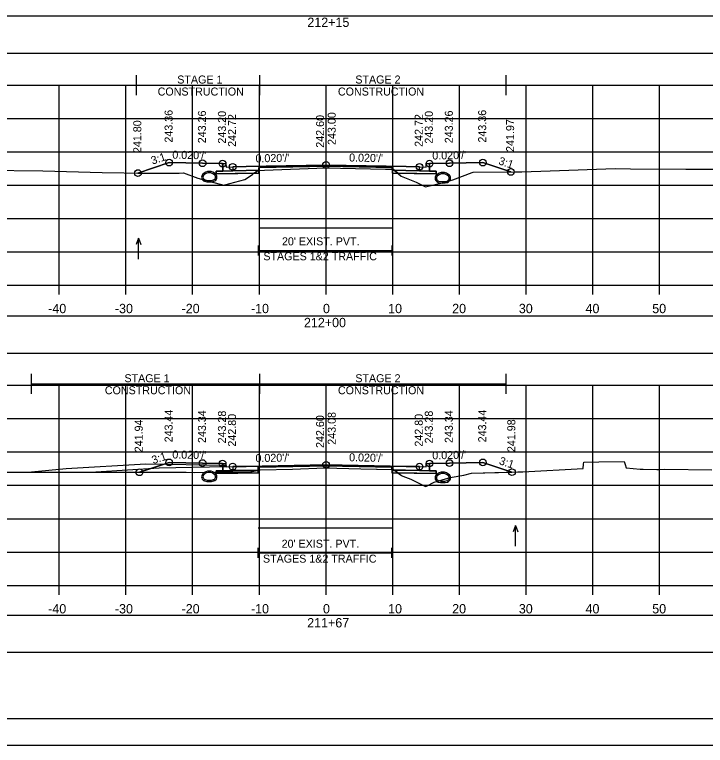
# Model space of a CAD drawing. Extents: x 1369627 to 1374022, y 380035 to 398173.
# Drawn here: x 1372051.8 to 1372155.4, y 382598.8 to 382708.4 of the extents above; entities that cross this region are included whole.
import ezdxf

# ---------------------------------------------------------------- set-up
doc = ezdxf.new("R2010")
doc.units = 0
for name, color, linetype in [('Default', 7, 'Continuous'), ('R_Alt Surface', 7, 'Continuous'), ('R_Axis', 7, 'Continuous'), ('R_Axis Annot', 7, 'Continuous'), ('R_Border', 7, 'Continuous'), ('R_Drive', 7, 'Continuous'), ('R_Exist Surface', 7, 'Continuous'), ('R_Fin Surface', 7, 'Continuous'), ('R_Grid', 7, 'Continuous'), ('R_MOT', 7, 'Continuous'), ('R_No Plot', 7, 'Continuous'), ('R_Water Annot', 7, 'Continuous'), ('R_Xsect Elev', 7, 'Continuous'), ('R_Xsect Slope', 7, 'Continuous'), ('T_Vehicle Path Lt Minor', 7, 'Continuous'), ('T_Vehicle Path Rt', 7, 'Continuous')]:
    doc.layers.add(name, color=color, linetype=linetype)

msp = doc.modelspace()

# ---------------------------------------------------------------- linework, layer by layer
at = {"layer": 'Default'}
for p, q in [((1372088.42, 382672.27), (1372088.42, 382673.77)), ((1372088.42, 382673.02), (1372108.42, 382673.02)), ((1372108.42, 382672.27), (1372108.42, 382673.77)), ((1372088.37, 382626.96), (1372088.37, 382628.46)), ((1372108.37, 382626.96), (1372108.37, 382628.46)), ((1372088.37, 382627.71), (1372108.37, 382627.71))]:
    msp.add_line(p, q, dxfattribs=at)
for points in [[(1371948.53, 382702.6), (1372248.53, 382702.6), (1372248.53, 382708.12), (1371948.53, 382708.12)], [(1372083.02, 382686.02), (1372083.52, 382686.02), (1372083.53, 382685.52), (1372084.53, 382685.54), (1372084.53, 382684.95), (1372083.03, 382684.92)], [(1372113.53, 382685.52), (1372113.54, 382686.02), (1372114.04, 382686.02), (1372114.03, 382684.92), (1372112.53, 382684.95), (1372112.53, 382685.54)], [(1371948.53, 382657.63), (1372248.53, 382657.63), (1372248.53, 382663.15), (1371948.53, 382663.15)], [(1372083.02, 382641.09), (1372083.52, 382641.09), (1372083.53, 382640.59), (1372084.53, 382640.61), (1372084.53, 382640.02), (1372083.03, 382639.99)], [(1372113.53, 382640.59), (1372113.54, 382641.09), (1372114.04, 382641.09), (1372114.03, 382639.99), (1372112.53, 382640.02), (1372112.53, 382640.61)], [(1371948.53, 382612.78), (1372248.53, 382612.78), (1372248.53, 382618.3), (1371948.53, 382618.3)]]:
    msp.add_lwpolyline(points, close=True, dxfattribs=at)
at = {"layer": 'R_Alt Surface'}
for points in [[(1372082.03, 382684.9), (1372083.03, 382684.92), (1372084.53, 382684.95), (1372088.43, 382685.03), (1372088.43, 382684.61), (1372082.03, 382684.48)], [(1372115.03, 382684.9), (1372114.03, 382684.92), (1372112.53, 382684.95), (1372108.43, 382685.03), (1372108.43, 382684.62), (1372115.03, 382684.48)], [(1372082.03, 382639.97), (1372083.03, 382639.99), (1372084.53, 382640.02), (1372088.37, 382640.1), (1372088.37, 382639.68), (1372082.03, 382639.56)], [(1372115.03, 382639.97), (1372114.03, 382639.99), (1372112.53, 382640.02), (1372108.37, 382640.11), (1372108.37, 382639.69), (1372115.03, 382639.56)]]:
    msp.add_lwpolyline(points, close=True, dxfattribs=at)
for points in [[(1372083.03, 382686.02), (1372083.03, 382684.92), (1372084.53, 382684.95), (1372088.43, 382685.03), (1372088.43, 382685.45), (1372098.53, 382685.65), (1372108.43, 382685.45), (1372108.43, 382685.03), (1372112.53, 382684.95), (1372114.03, 382684.92), (1372114.03, 382686.02)], [(1372083.03, 382641.09), (1372083.03, 382639.99), (1372084.53, 382640.02), (1372088.37, 382640.1), (1372088.37, 382640.52), (1372098.53, 382640.72), (1372108.37, 382640.52), (1372108.37, 382640.11), (1372112.53, 382640.02), (1372114.03, 382639.99), (1372114.03, 382641.09)]]:
    msp.add_lwpolyline(points, dxfattribs=at)
at = {"layer": 'R_Axis'}
for p, q in [((1371948.53, 382667.81), (1372248.53, 382667.81)), ((1372058.53, 382666.41), (1372058.53, 382667.81)), ((1372068.53, 382666.41), (1372068.53, 382667.81)), ((1372078.53, 382666.41), (1372078.53, 382667.81)), ((1372088.53, 382666.41), (1372088.53, 382667.81)), ((1372098.53, 382666.41), (1372098.53, 382667.81)), ((1372108.53, 382666.41), (1372108.53, 382667.81)), ((1372118.53, 382666.41), (1372118.53, 382667.81)), ((1372128.53, 382666.41), (1372128.53, 382667.81)), ((1372138.53, 382666.41), (1372138.53, 382667.81)), ((1372148.53, 382666.41), (1372148.53, 382667.81)), ((1371948.53, 382622.81), (1372248.53, 382622.81)), ((1372058.53, 382621.41), (1372058.53, 382622.81)), ((1372068.53, 382621.41), (1372068.53, 382622.81)), ((1372078.53, 382621.41), (1372078.53, 382622.81)), ((1372088.53, 382621.41), (1372088.53, 382622.81)), ((1372098.53, 382621.41), (1372098.53, 382622.81)), ((1372108.53, 382621.41), (1372108.53, 382622.81)), ((1372118.53, 382621.41), (1372118.53, 382622.81)), ((1372128.53, 382621.41), (1372128.53, 382622.81)), ((1372138.53, 382621.41), (1372138.53, 382622.81)), ((1372148.53, 382621.41), (1372148.53, 382622.81))]:
    msp.add_line(p, q, dxfattribs=at)
at = {"layer": 'R_Border'}
msp.add_line((1372256.71, 382602.81), (1371940.53, 382602.81), dxfattribs=at)
at = {"layer": 'R_Drive'}
for p, q in [((1372059.55, 382640.28), (1372054.37, 382639.76)), ((1372071.53, 382641), (1372059.55, 382640.28))]:
    msp.add_line(p, q, dxfattribs=at)
msp.add_lwpolyline([(1372083.53, 382640.59), (1372083.53, 382640.76), (1372071.53, 382641)], dxfattribs=at)
for centre, radius, start, end in [((1372080.51, 382684), 0.646, 136.3515, 253.9529), ((1372081.02, 382683.51), 1.35, 43.6485, 136.3515), ((1372080.51, 382684), 0.438, 136.3515, 253.9529), ((1372081.02, 382683.51), 1.15, 43.6485, 136.3515), ((1372081.53, 382684), 0.438, 286.0471, 43.6485), ((1372081.53, 382684), 0.646, 286.0471, 43.6485), ((1372115.53, 382683.84), 0.646, 136.3515, 253.9529), ((1372116.04, 382683.35), 1.35, 43.6485, 136.3515), ((1372115.53, 382683.84), 0.438, 136.3515, 253.9529), ((1372116.04, 382683.35), 1.15, 43.6485, 136.3515), ((1372116.55, 382683.84), 0.438, 286.0471, 43.6485), ((1372116.55, 382683.84), 0.646, 286.0471, 43.6485), ((1372081.02, 382685.78), 2.5, 253.9529, 286.0471), ((1372081.02, 382685.78), 2.29, 253.9529, 286.0471), ((1372116.04, 382685.62), 2.5, 253.9529, 286.0471), ((1372116.04, 382685.62), 2.29, 253.9529, 286.0471), ((1372080.51, 382639.08), 0.646, 136.3515, 253.9529), ((1372081.02, 382638.6), 1.35, 43.6485, 136.3515), ((1372080.51, 382639.08), 0.438, 136.3515, 253.9529), ((1372081.02, 382638.6), 1.15, 43.6485, 136.3515), ((1372081.53, 382639.08), 0.438, 286.0471, 43.6485), ((1372081.53, 382639.08), 0.646, 286.0471, 43.6485), ((1372115.53, 382638.92), 0.646, 136.3515, 253.9529), ((1372116.04, 382638.44), 1.35, 43.6485, 136.3515), ((1372115.53, 382638.92), 0.438, 136.3515, 253.9529), ((1372116.04, 382638.44), 1.15, 43.6485, 136.3515), ((1372116.55, 382638.92), 0.438, 286.0471, 43.6485), ((1372116.55, 382638.92), 0.646, 286.0471, 43.6485), ((1372081.02, 382640.87), 2.5, 253.9529, 286.0471), ((1372081.02, 382640.87), 2.29, 253.9529, 286.0471), ((1372116.04, 382640.71), 2.5, 253.9529, 286.0471), ((1372116.04, 382640.71), 2.29, 253.9529, 286.0471)]:
    msp.add_arc(centre, radius, start, end, dxfattribs=at)
at = {"layer": 'R_Exist Surface'}
for points in [[(1372047.35, 382685.06), (1372056.07, 382684.93), (1372064.97, 382684.69), (1372071.52, 382684.6), (1372076.49, 382684.59), (1372077.15, 382684.67), (1372079.33, 382683.86), (1372079.5, 382683.79), (1372079.65, 382683.76), (1372083.18, 382682.79), (1372083.33, 382682.83), (1372086.35, 382683.67), (1372087.48, 382684.42), (1372087.68, 382684.59), (1372088.05, 382684.82), (1372088.32, 382685), (1372089.29, 382685.04), (1372098.43, 382685.42), (1372107.46, 382685.21), (1372108.55, 382685.19), (1372108.7, 382685.08), (1372109.8, 382684.17), (1372112.04, 382683.23), (1372113.44, 382682.57), (1372116.15, 382683.22), (1372117.56, 382683.58), (1372120.42, 382684.69), (1372120.61, 382684.76), (1372126.88, 382684.78), (1372127.87, 382684.81), (1372132.12, 382684.95), (1372141.86, 382685.29), (1372144.17, 382685.26), (1372152.48, 382685.18), (1372158.04, 382685.21)], [(1372048.59, 382639.76), (1372057.66, 382639.76), (1372073.4, 382639.76), (1372077.58, 382639.78), (1372078.84, 382639.72), (1372082.4, 382639.77), (1372082.8, 382639.77), (1372083.45, 382639.81), (1372086.69, 382639.79), (1372086.85, 382639.79), (1372086.97, 382639.79), (1372086.99, 382639.8), (1372088.63, 382640.11), (1372093.49, 382640.25), (1372098.37, 382640.42), (1372103.74, 382640.28), (1372108.64, 382640.16), (1372109.82, 382639.3), (1372110.02, 382639.18), (1372111.23, 382638.72), (1372113.03, 382637.83), (1372113.35, 382637.68), (1372113.44, 382637.64), (1372113.58, 382637.69), (1372114.75, 382638.28), (1372117.13, 382638.97), (1372119.17, 382639.33), (1372120.35, 382639.62), (1372127.31, 382639.82), (1372127.34, 382639.82), (1372127.5, 382639.83), (1372128.02, 382639.85), (1372137.09, 382640.33), (1372137.15, 382640.98), (1372137.18, 382641.29), (1372139.42, 382641.33), (1372143.24, 382641.4), (1372143.4, 382640.91), (1372143.53, 382640.45), (1372145.65, 382640.21), (1372146.07, 382640.22), (1372148.12, 382640.2), (1372148.24, 382640.2), (1372148.43, 382640.2), (1372149.35, 382640.22), (1372156.36, 382640.13)]]:
    msp.add_lwpolyline(points, dxfattribs=at)
at = {"layer": 'R_Fin Surface'}
for points in [[(1372070.33, 382684.61), (1372075.02, 382686.18), (1372080.02, 382686.08), (1372083.02, 382686.02), (1372083.52, 382686.02), (1372083.53, 382685.52), (1372084.53, 382685.54), (1372086.53, 382685.58), (1372098.53, 382685.82), (1372110.53, 382685.58), (1372112.53, 382685.54), (1372113.53, 382685.52), (1372113.54, 382686.02), (1372114.04, 382686.02), (1372117.04, 382686.08), (1372122.04, 382686.18), (1372126.23, 382684.78)], [(1372070.54, 382639.76), (1372075.02, 382641.25), (1372080.02, 382641.15), (1372083.02, 382641.09), (1372083.52, 382641.09), (1372083.53, 382640.59), (1372084.53, 382640.61), (1372086.53, 382640.65), (1372098.53, 382640.89), (1372110.53, 382640.65), (1372112.53, 382640.61), (1372113.53, 382640.59), (1372113.54, 382641.09), (1372114.04, 382641.09), (1372117.04, 382641.15), (1372122.04, 382641.25), (1372126.41, 382639.79)]]:
    msp.add_lwpolyline(points, dxfattribs=at)
at = {"layer": 'R_Grid'}
for p, q in [((1371948.53, 382697.81), (1372248.53, 382697.81)), ((1372058.53, 382667.81), (1372058.53, 382697.81)), ((1372068.53, 382667.81), (1372068.53, 382697.81)), ((1372078.53, 382667.81), (1372078.53, 382697.81)), ((1372088.53, 382667.81), (1372088.53, 382697.81)), ((1372098.53, 382667.81), (1372098.53, 382697.81)), ((1372108.53, 382667.81), (1372108.53, 382697.81)), ((1372118.53, 382667.81), (1372118.53, 382697.81)), ((1372128.53, 382667.81), (1372128.53, 382697.81)), ((1372138.53, 382667.81), (1372138.53, 382697.81)), ((1372148.53, 382667.81), (1372148.53, 382697.81)), ((1371948.53, 382692.81), (1372248.53, 382692.81)), ((1371948.53, 382687.81), (1372248.53, 382687.81)), ((1371948.53, 382682.81), (1372248.53, 382682.81)), ((1371948.53, 382677.81), (1372248.53, 382677.81)), ((1371948.53, 382672.81), (1372248.53, 382672.81)), ((1371948.53, 382667.81), (1372248.53, 382667.81)), ((1371948.53, 382652.81), (1372248.53, 382652.81)), ((1372058.53, 382622.81), (1372058.53, 382652.81)), ((1372068.53, 382622.81), (1372068.53, 382652.81)), ((1372078.53, 382622.81), (1372078.53, 382652.81)), ((1372088.53, 382622.81), (1372088.53, 382652.81)), ((1372098.53, 382622.81), (1372098.53, 382652.81)), ((1372108.53, 382622.81), (1372108.53, 382652.81)), ((1372118.53, 382622.81), (1372118.53, 382652.81)), ((1372128.53, 382622.81), (1372128.53, 382652.81)), ((1372138.53, 382622.81), (1372138.53, 382652.81)), ((1372148.53, 382622.81), (1372148.53, 382652.81)), ((1371948.53, 382647.81), (1372248.53, 382647.81)), ((1371948.53, 382642.81), (1372248.53, 382642.81)), ((1371948.53, 382637.81), (1372248.53, 382637.81)), ((1371948.53, 382632.81), (1372248.53, 382632.81)), ((1371948.53, 382627.81), (1372248.53, 382627.81)), ((1371948.53, 382622.81), (1372248.53, 382622.81))]:
    msp.add_line(p, q, dxfattribs=at)
at = {"layer": 'R_MOT'}
for p, q in [((1372070.11, 382696.27), (1372070.11, 382699.27)), ((1372088.58, 382696.27), (1372088.58, 382699.27)), ((1372125.56, 382696.27), (1372125.56, 382699.27)), ((1372070.11, 382697.77), (1372125.56, 382697.77)), ((1372054.37, 382651.5), (1372054.37, 382654.5)), ((1372088.58, 382651.5), (1372088.58, 382654.5)), ((1372125.56, 382651.5), (1372125.56, 382654.5)), ((1372054.37, 382653), (1372125.56, 382653))]:
    msp.add_line(p, q, dxfattribs=at)
at = {"layer": 'R_No Plot'}
for p, q in [((1372073.53, 382640.39), (1372063.99, 382639.76)), ((1372083.53, 382640.59), (1372073.53, 382640.39)), ((1371928.13, 382598.84), (1372261.46, 382598.84))]:
    msp.add_line(p, q, dxfattribs=at)
for points in [[(1371928.12, 382812.17), (1372261.46, 382812.17), (1372261.46, 382598.83), (1371928.12, 382598.83)], [(1372174.45, 382808.27), (1372194.07, 382808.27), (1372194.07, 382798.39), (1372210.18, 382798.39), (1372233.38, 382798.39), (1372233.38, 382765.72), (1372256.59, 382765.72), (1372256.71, 382602.81), (1371940.53, 382602.81), (1371940.53, 382808.27)], [(1372088.53, 382685.03), (1372084.53, 382684.95), (1372083.03, 382684.92), (1372082.03, 382684.9), (1372082.03, 382684.48), (1372088.53, 382684.61)], [(1372098.53, 382685.82), (1372086.53, 382685.58), (1372084.53, 382685.54), (1372084.53, 382684.95), (1372088.53, 382685.03), (1372088.53, 382685.45), (1372098.53, 382685.65), (1372108.53, 382685.45), (1372108.53, 382685.03), (1372112.53, 382684.95), (1372112.53, 382685.54), (1372110.53, 382685.58)], [(1372108.53, 382685.03), (1372112.53, 382684.95), (1372114.03, 382684.92), (1372115.03, 382684.9), (1372115.03, 382684.48), (1372108.53, 382684.61)], [(1372088.53, 382640.1), (1372084.53, 382640.02), (1372083.03, 382639.99), (1372082.03, 382639.97), (1372082.03, 382639.56), (1372088.53, 382639.69)], [(1372098.53, 382640.89), (1372086.53, 382640.65), (1372084.53, 382640.61), (1372084.53, 382640.02), (1372088.53, 382640.1), (1372088.53, 382640.52), (1372098.53, 382640.72), (1372108.53, 382640.52), (1372108.53, 382640.1), (1372112.53, 382640.02), (1372112.53, 382640.61), (1372110.53, 382640.65)], [(1372108.53, 382640.1), (1372112.53, 382640.02), (1372114.03, 382639.99), (1372115.03, 382639.97), (1372115.03, 382639.56), (1372108.53, 382639.69)]]:
    msp.add_lwpolyline(points, close=True, dxfattribs=at)
for points in [[(1372083.02, 382686.02), (1372083.03, 382684.92), (1372084.53, 382684.95), (1372088.53, 382685.03), (1372088.53, 382685.45), (1372098.53, 382685.65), (1372108.53, 382685.45), (1372108.53, 382685.03), (1372112.53, 382684.95), (1372114.03, 382684.92), (1372114.04, 382686.02)], [(1372088.43, 382676.42), (1372108.43, 382676.42)], [(1372083.02, 382641.09), (1372083.03, 382639.99), (1372084.53, 382640.02), (1372088.53, 382640.1), (1372088.53, 382640.52), (1372098.53, 382640.72), (1372108.53, 382640.52), (1372108.53, 382640.1), (1372112.53, 382640.02), (1372114.03, 382639.99), (1372114.04, 382641.09)], [(1372088.37, 382631.42), (1372108.37, 382631.42)]]:
    msp.add_lwpolyline(points, dxfattribs=at)
for centre in [(1372075.02, 382686.18), (1372080.02, 382686.08), (1372083.02, 382686.02), (1372098.53, 382685.82), (1372114.04, 382686.02), (1372117.04, 382686.08), (1372122.04, 382686.18), (1372070.33, 382684.61), (1372084.53, 382685.54), (1372112.53, 382685.54), (1372126.23, 382684.78), (1372075.02, 382641.25), (1372080.02, 382641.15), (1372083.02, 382641.09), (1372098.53, 382640.89), (1372114.04, 382641.09), (1372117.04, 382641.15), (1372122.04, 382641.25), (1372070.54, 382639.76), (1372084.53, 382640.61), (1372112.53, 382640.61), (1372126.41, 382639.79)]:
    msp.add_circle(centre, 0.5, dxfattribs=at)
at = {"layer": 'R_Water Annot'}
for p, q in [((1372070.41, 382674.87), (1372070.06, 382673.91)), ((1372070.41, 382671.73), (1372070.41, 382674.87)), ((1372070.41, 382674.87), (1372070.76, 382673.91)), ((1372126.93, 382631.81), (1372126.58, 382630.85)), ((1372126.93, 382628.67), (1372126.93, 382631.81)), ((1372126.93, 382631.81), (1372127.28, 382630.85))]:
    msp.add_line(p, q, dxfattribs=at)
at = {"layer": 'R_Xsect Elev'}
for p, q in [((1372098.53, 382685.41), (1372098.53, 382695.41)), ((1372098.53, 382640.41), (1372098.53, 382650.41))]:
    msp.add_line(p, q, dxfattribs=at)
at = {"layer": 'T_Vehicle Path Lt Minor'}
for p, q in [((1372059.55, 382640.28), (1372054.37, 382639.76)), ((1372071.53, 382641), (1372059.55, 382640.28)), ((1372070.54, 382639.76), (1372074.11, 382640.95)), ((1372074.11, 382640.95), (1372071.53, 382641))]:
    msp.add_line(p, q, dxfattribs=at)
msp.add_lwpolyline([(1372054.37, 382639.76), (1372057.66, 382639.76), (1372070.54, 382639.76)], dxfattribs=at)
at = {"layer": 'T_Vehicle Path Rt'}
for p, q in [((1372083.03, 382684.92), (1372083.02, 382686.02)), ((1372088.43, 382685), (1372088.32, 382685)), ((1372088.43, 382685.03), (1372088.43, 382685)), ((1372088.43, 382684.61), (1372088.43, 382685)), ((1372108.43, 382685.19), (1372108.43, 382685.45)), ((1372108.43, 382685.19), (1372108.43, 382685.03)), ((1372108.76, 382685.03), (1372108.43, 382685.03)), ((1372108.43, 382685.03), (1372108.76, 382685.03)), ((1372109.28, 382684.6), (1372108.76, 382685.03)), ((1372114.04, 382686.02), (1372114.03, 382684.92)), ((1372087.68, 382684.6), (1372082.03, 382684.48)), ((1372087.48, 382684.42), (1372087.68, 382684.59)), ((1372087.69, 382684.6), (1372088.43, 382684.61)), ((1372109.28, 382684.6), (1372109.8, 382684.17)), ((1372083.03, 382639.99), (1372083.02, 382641.09)), ((1372088.37, 382640.1), (1372088.37, 382640.06)), ((1372108.37, 382640.17), (1372108.37, 382640.52)), ((1372108.37, 382640.17), (1372108.37, 382640.11)), ((1372108.72, 382640.1), (1372108.37, 382640.11)), ((1372108.37, 382640.11), (1372108.72, 382640.1)), ((1372109.31, 382639.67), (1372108.72, 382640.1)), ((1372114.04, 382641.09), (1372114.03, 382639.99)), ((1372082.03, 382639.97), (1372083.03, 382639.99)), ((1372082.03, 382639.76), (1372082.03, 382639.97)), ((1372082.03, 382639.76), (1372082.03, 382639.56))]:
    msp.add_line(p, q, dxfattribs=at)
for points in [[(1372083.02, 382686.02), (1372080.02, 382686.08), (1372075.02, 382686.18), (1372070.33, 382684.61)], [(1372126.23, 382684.78), (1372122.04, 382686.18), (1372117.04, 382686.08), (1372114.04, 382686.02)], [(1372088.32, 382685), (1372088.05, 382684.82), (1372087.69, 382684.6)], [(1372108.43, 382685.45), (1372098.53, 382685.65), (1372088.43, 382685.45), (1372088.43, 382685.03)], [(1372088.43, 382685), (1372089.29, 382685.04), (1372098.43, 382685.42), (1372107.46, 382685.21), (1372108.43, 382685.19)], [(1372108.76, 382685.03), (1372108.7, 382685.08), (1372108.55, 382685.19), (1372108.43, 382685.19)], [(1372108.43, 382685.03), (1372108.43, 382684.62), (1372109.28, 382684.6)], [(1372070.33, 382684.61), (1372071.52, 382684.6), (1372076.49, 382684.59), (1372077.15, 382684.67), (1372079.33, 382683.86), (1372079.5, 382683.79), (1372079.65, 382683.76), (1372083.18, 382682.79), (1372083.33, 382682.83), (1372086.35, 382683.67), (1372087.48, 382684.42)], [(1372082.03, 382684.48), (1372082.03, 382684.9), (1372083.03, 382684.92)], [(1372087.68, 382684.59), (1372087.68, 382684.6)], [(1372114.03, 382684.92), (1372115.03, 382684.9), (1372115.03, 382684.48), (1372109.28, 382684.6)], [(1372109.8, 382684.17), (1372112.04, 382683.23), (1372113.44, 382682.57), (1372116.15, 382683.22), (1372117.56, 382683.58), (1372120.42, 382684.69), (1372120.61, 382684.76), (1372126.23, 382684.78)], [(1372083.02, 382641.09), (1372080.02, 382641.15), (1372075.02, 382641.25), (1372070.54, 382639.76)], [(1372126.41, 382639.79), (1372122.04, 382641.25), (1372117.04, 382641.15), (1372114.04, 382641.09)], [(1372108.37, 382640.52), (1372098.53, 382640.72), (1372088.37, 382640.52), (1372088.37, 382640.1)], [(1372088.37, 382640.06), (1372088.63, 382640.11), (1372093.49, 382640.25), (1372098.37, 382640.42), (1372103.74, 382640.28), (1372108.37, 382640.17)], [(1372108.72, 382640.1), (1372108.64, 382640.16), (1372108.37, 382640.17)], [(1372108.37, 382640.11), (1372108.37, 382639.69), (1372109.31, 382639.67)], [(1372070.54, 382639.76), (1372073.4, 382639.76), (1372077.58, 382639.78), (1372078.84, 382639.72), (1372082.03, 382639.76)], [(1372082.03, 382639.56), (1372088.37, 382639.68), (1372088.37, 382640.06)], [(1372088.37, 382640.06), (1372086.99, 382639.8), (1372086.97, 382639.79), (1372086.85, 382639.79), (1372086.69, 382639.79), (1372083.45, 382639.81), (1372082.8, 382639.77), (1372082.4, 382639.77), (1372082.03, 382639.76)], [(1372114.03, 382639.99), (1372115.03, 382639.97), (1372115.03, 382639.56), (1372109.31, 382639.67)], [(1372109.31, 382639.67), (1372109.55, 382639.5), (1372109.82, 382639.3)], [(1372109.82, 382639.3), (1372110.02, 382639.18), (1372111.23, 382638.72), (1372113.03, 382637.83), (1372113.35, 382637.68), (1372113.44, 382637.64), (1372113.58, 382637.69), (1372114.75, 382638.28), (1372117.13, 382638.97), (1372119.17, 382639.33), (1372120.35, 382639.62), (1372126.41, 382639.79)]]:
    msp.add_lwpolyline(points, dxfattribs=at)

# ---------------------------------------------------------------- texts
at = {"layer": 'R_Axis Annot'}
for s, height, p in [('212+15', 1.4, (1372095.73, 382706.51)), ("20' EXIST. PVT.", 1.2, (1372091.92, 382673.78)), ('STAGES 1&2 TRAFFIC', 1.2, (1372089.13, 382671.54)), ('-40', 1.4, (1372056.87, 382663.61)), ('-30', 1.4, (1372066.87, 382663.61)), ('-20', 1.4, (1372076.87, 382663.61)), ('-10', 1.4, (1372087.27, 382663.61)), ('0', 1.4, (1372098.07, 382663.61)), ('10', 1.4, (1372107.84, 382663.61)), ('20', 1.4, (1372117.44, 382663.61)), ('30', 1.4, (1372127.44, 382663.61)), ('40', 1.4, (1372137.44, 382663.61)), ('50', 1.4, (1372147.44, 382663.61)), ('212+00', 1.4, (1372095.22, 382661.51)), ("20' EXIST. PVT.", 1.2, (1372091.87, 382628.46)), ('STAGES 1&2 TRAFFIC', 1.2, (1372089.07, 382626.22)), ('-40', 1.4, (1372056.87, 382618.61)), ('-30', 1.4, (1372066.87, 382618.61)), ('-20', 1.4, (1372076.87, 382618.61)), ('-10', 1.4, (1372087.27, 382618.61)), ('0', 1.4, (1372098.07, 382618.61)), ('10', 1.4, (1372107.84, 382618.61)), ('20', 1.4, (1372117.44, 382618.61)), ('30', 1.4, (1372127.44, 382618.61)), ('40', 1.4, (1372137.44, 382618.61)), ('50', 1.4, (1372147.44, 382618.61)), ('211+67', 1.4, (1372095.7, 382616.51))]:
    msp.add_text(s, height=height, dxfattribs=at).set_placement(p)
at = {"layer": 'R_MOT'}
for s, p in [('STAGE 1', (1372076.22, 382698.03)), ('STAGE 2', (1372102.92, 382698.03)), ('CONSTRUCTION', (1372073.28, 382696.23)), ('CONSTRUCTION', (1372100.31, 382696.23)), ('STAGE 1', (1372068.3, 382653.26)), ('STAGE 2', (1372102.92, 382653.26)), ('CONSTRUCTION', (1372065.36, 382651.46)), ('CONSTRUCTION', (1372100.31, 382651.46))]:
    msp.add_text(s, height=1.2, dxfattribs=at).set_placement(p)
at = {"layer": 'R_Xsect Elev'}
for s, p in [('243.36', (1372075.52, 382689.18)), ('243.26', (1372080.52, 382689.08)), ('243.20', (1372083.52, 382689.02)), ('243.20', (1372114.54, 382689.02)), ('243.26', (1372117.54, 382689.08)), ('243.36', (1372122.54, 382689.18)), ('242.72', (1372085.03, 382688.54)), ('242.60', (1372098.23, 382688.41)), ('243.00', (1372099.98, 382688.82)), ('242.72', (1372113.03, 382688.54)), ('241.80', (1372070.83, 382687.61)), ('241.97', (1372126.73, 382687.78)), ('243.44', (1372075.52, 382644.25)), ('243.34', (1372080.52, 382644.15)), ('243.28', (1372083.52, 382644.09)), ('243.28', (1372114.54, 382644.09)), ('243.34', (1372117.54, 382644.15)), ('243.44', (1372122.54, 382644.25)), ('242.80', (1372085.03, 382643.61)), ('242.60', (1372098.23, 382643.41)), ('243.08', (1372099.98, 382643.89)), ('242.80', (1372113.03, 382643.61)), ('241.94', (1372071.04, 382642.76)), ('241.98', (1372126.91, 382642.79))]:
    msp.add_text(s, height=1.2, rotation=90, dxfattribs=at).set_placement(p)
at = {"layer": 'R_Xsect Slope'}
for s, rotation, p in [('3:1', 18.4332, (1372072.51, 382685.87)), ("0.020'/'", 358.8542, (1372075.47, 382686.77)), ("0.020'/'", 1.1458, (1372087.96, 382686.21)), ("0.020'/'", 358.8542, (1372101.98, 382686.35)), ("0.020'/'", 1.1458, (1372114.47, 382686.63)), ('3:1', 341.5668, (1372124.29, 382685.95)), ('3:1', 18.4332, (1372072.62, 382640.98)), ("0.020'/'", 358.8542, (1372075.47, 382641.84)), ("0.020'/'", 1.1458, (1372087.96, 382641.28)), ("0.020'/'", 358.8542, (1372101.98, 382641.42)), ("0.020'/'", 1.1458, (1372114.47, 382641.7)), ('3:1', 341.5668, (1372124.38, 382641))]:
    msp.add_text(s, height=1.2, rotation=rotation, dxfattribs=at).set_placement(p)

doc.saveas('drawing.dxf')
